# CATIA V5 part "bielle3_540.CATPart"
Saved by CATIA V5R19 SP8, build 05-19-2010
Part number: elt3
Bounding box of the stored display mesh (mm): x -19.998 to 19.998, y 0 to 20, z -108.889 to 108.889
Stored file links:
  D:\Dropbox\CIAO82010_JCF\VIGUIER\0540-VIGUIER\CAO\bielle3_540.CATPart
  D:\Dropbox\CIAO82010_JCF\VIGUIER\0540-VIGUIER\CAO\0540.CATProduct
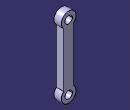
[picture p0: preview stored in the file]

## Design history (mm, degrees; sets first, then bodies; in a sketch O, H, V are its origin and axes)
External parameters (linked from other documents)
  External.longueur_bielles = 200 mm
  External.rayon_assemblage = 10 mm
AxisSystem1: origin (0, 0, 0), X (1, 0, 0), Y (0, 1, 0), Z (0, 0, 1)
Body1 (main body)
  Sketch1 on ZX plane of AxisSystem1, origin (0, 0, 0), H (0, 0, 1), V (1, 0, 0)
    arc A1 centre (-88.8889, 0) radius 20 from (-74.4613, 13.8508) to (-74.4613, -13.8508) ccw
    point P1 (-88.8889, 0)
    point P2 (-74.4613, 13.8508)
    point P3 (-74.4613, -13.8508)
    arc A2 centre (88.8889, 0) radius 20 from (74.4362, -13.8247) to (74.4362, 13.8247) ccw
    point P4 (88.8889, 0)
    point P5 (74.4362, -13.8247)
    point P6 (74.4362, 13.8247)
    line L1 (-74.4613, 13.8508) -> (74.4362, 13.8247)
    line L2 (-74.4613, -13.8508) -> (74.4362, -13.8247)
    radius A2 = 20 {= 2*External.rayon_assemblage}
    radius A1 = 20 {= 2*External.rayon_assemblage}
    distance P4 P1 = 177.7778 {= External.longueur_bielles /1.125}
    coincidence: P1 H, P4 H
    symmetry: P1 P4 V, P2 P3 H, P6 P5 H
  Pad1: profile Sketch1, direction (0, 1, 0), length 20
  Sketch2 on start face of Pad1, origin (0, 0, 0), H (1, 0, 0), V (0, 0, 1)
    circle A1 centre (0, 88.8889) radius 10
    point P1 (0, 88.8889)
    reference projected arc E1 centre (0, 88.8889) radius 20 from (13.8247, 74.4362) to (-13.8247, 74.4362) ccw from edge [start face of Pad1 | face of Pad1 from Sketch1.A2]
    circle A2 centre (0, -88.8889) radius 10
    radius A1 = 10 {= External.rayon_assemblage}
    coincidence: P1 V
    concentricity: P1 E1
    symmetry: A1 A2 H
  Pocket1: profile Sketch2, direction (0, 1, 0), through (limit type 3)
